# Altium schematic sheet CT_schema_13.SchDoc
size 629 x 471 mm
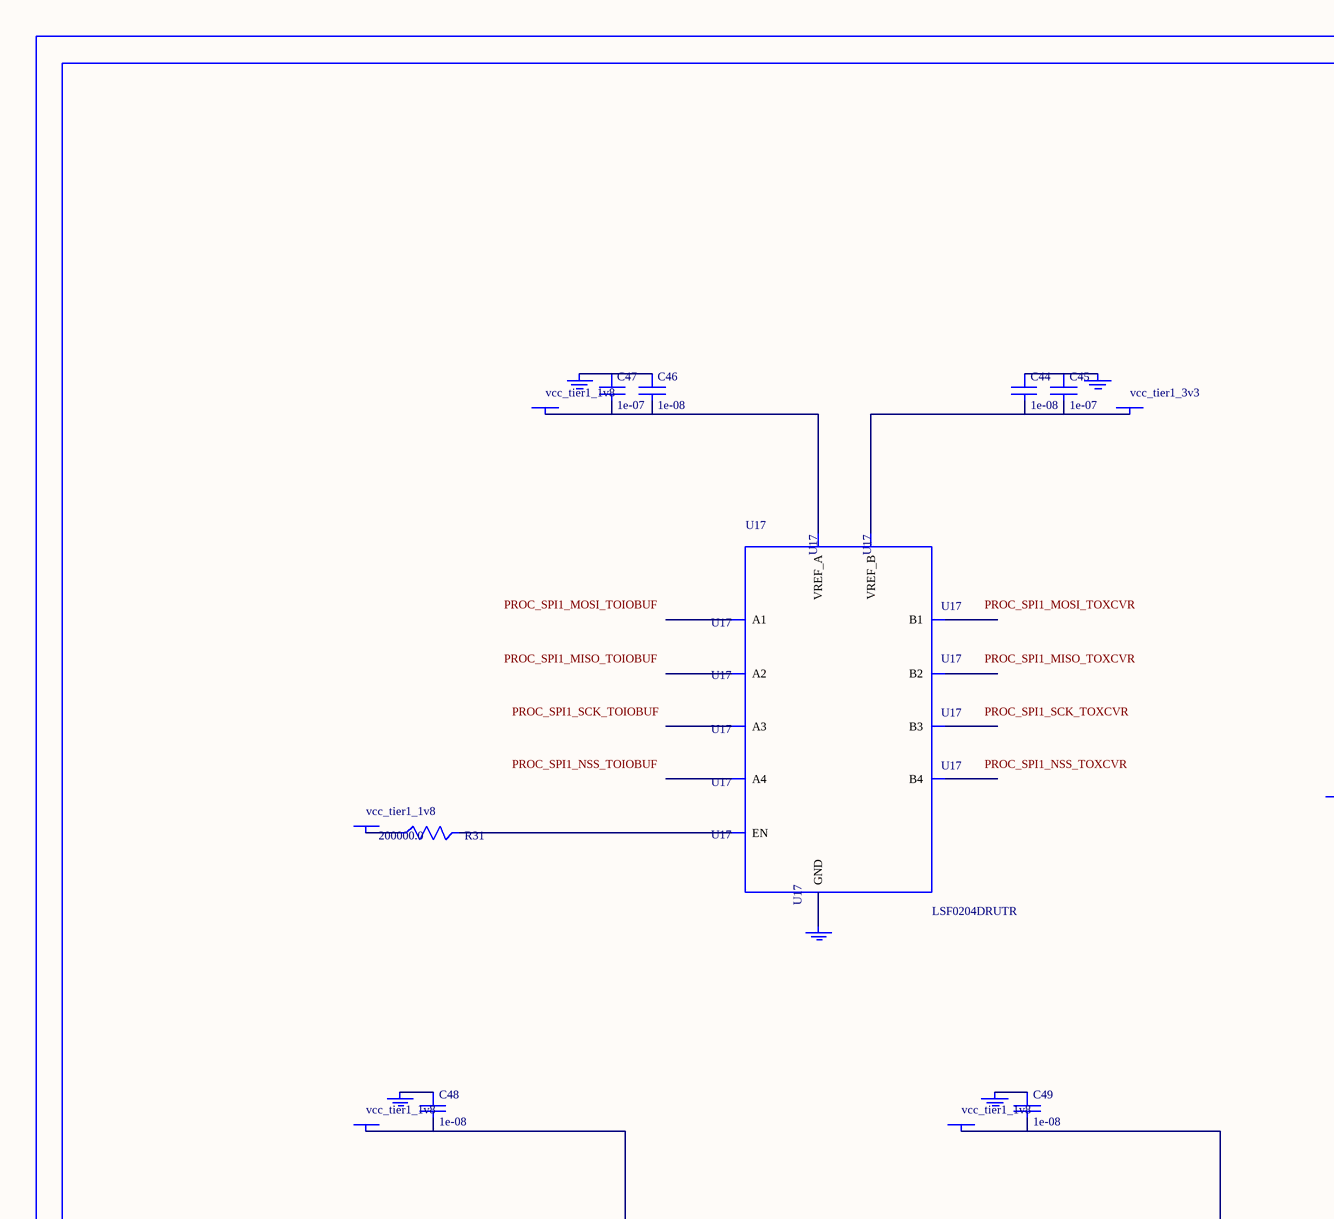
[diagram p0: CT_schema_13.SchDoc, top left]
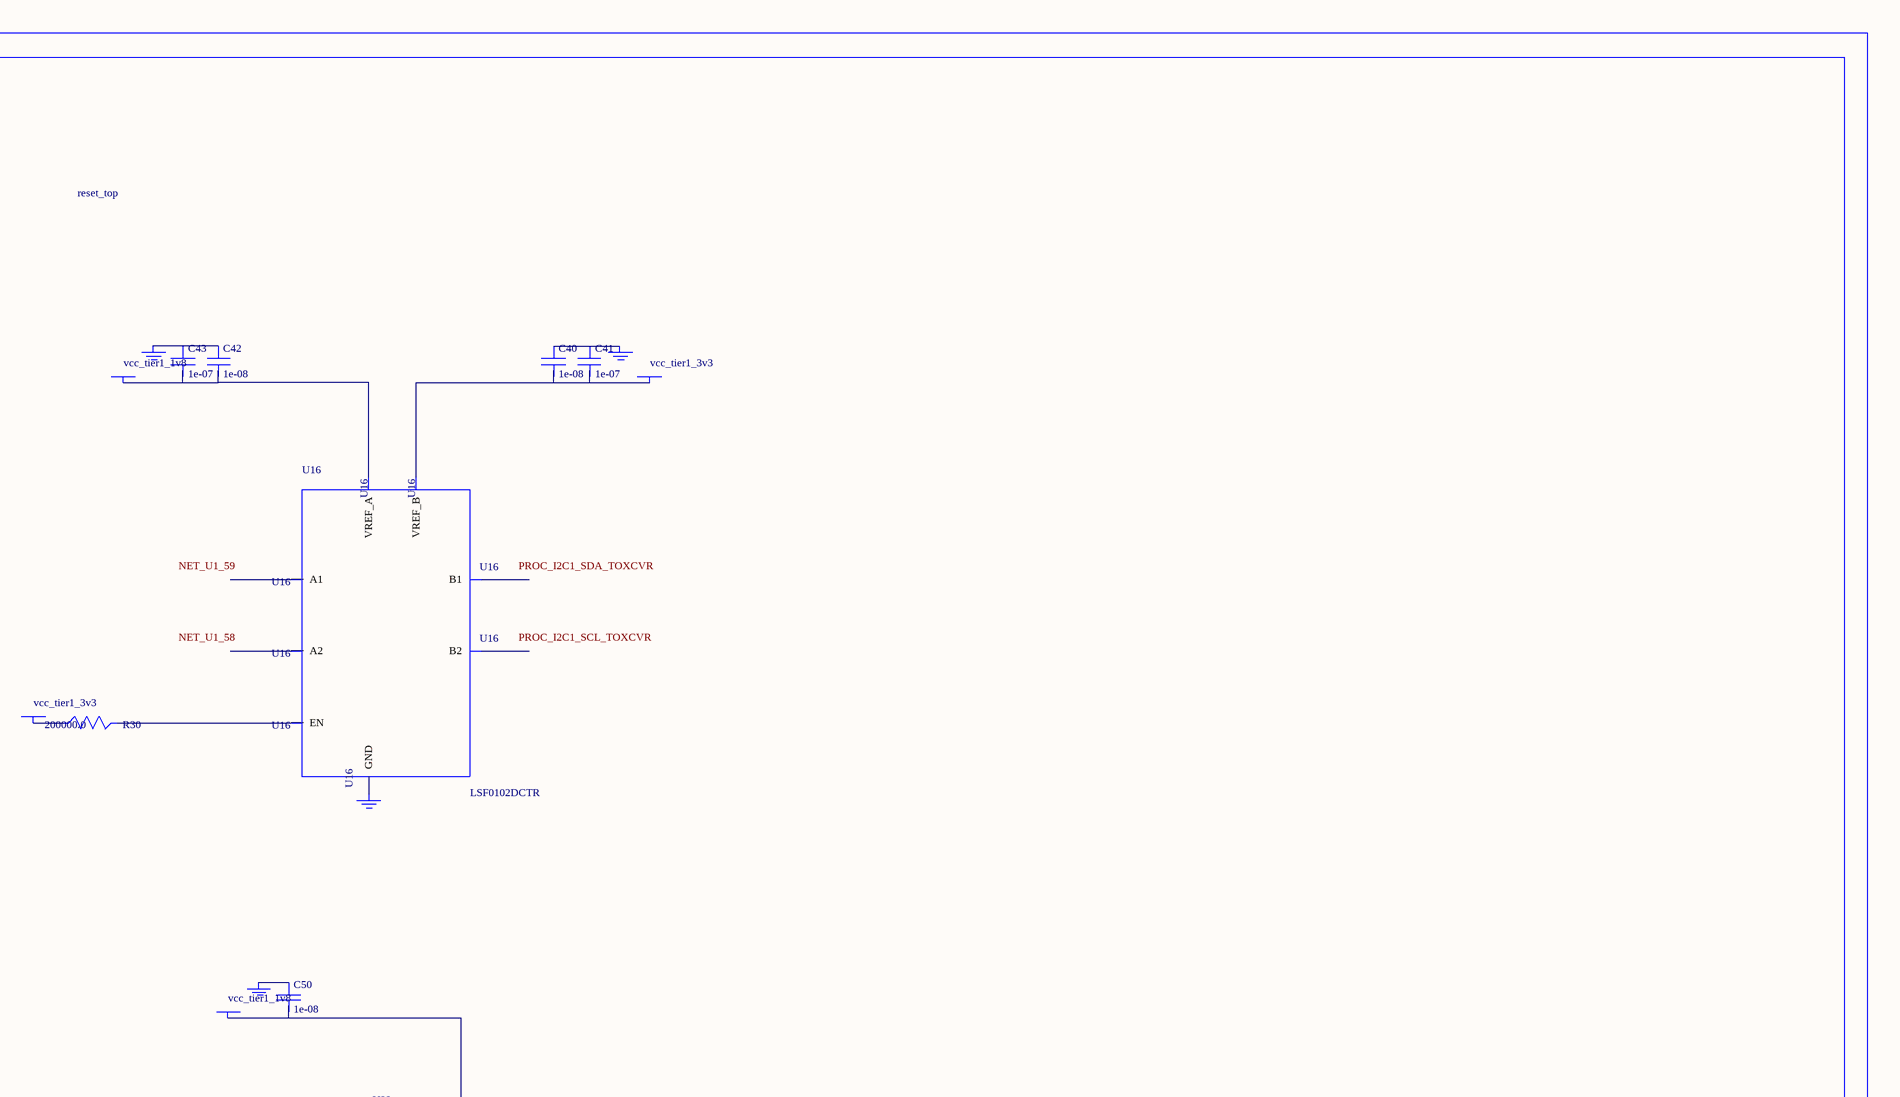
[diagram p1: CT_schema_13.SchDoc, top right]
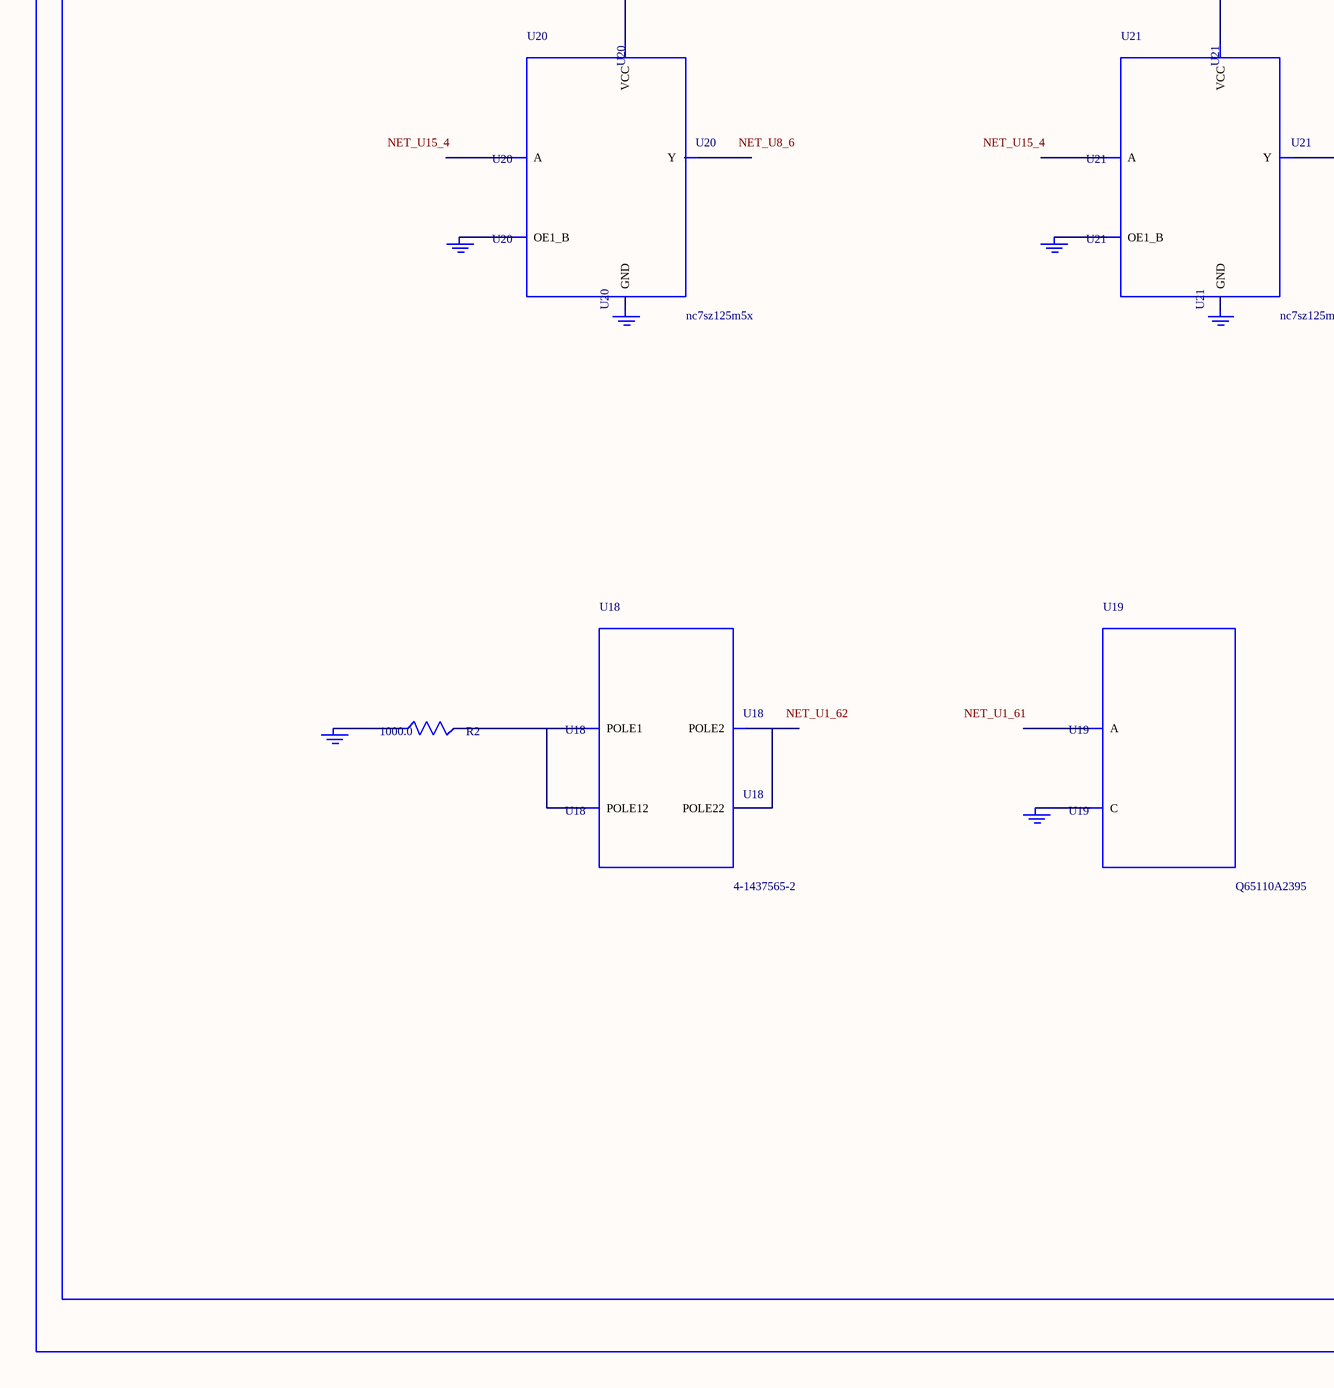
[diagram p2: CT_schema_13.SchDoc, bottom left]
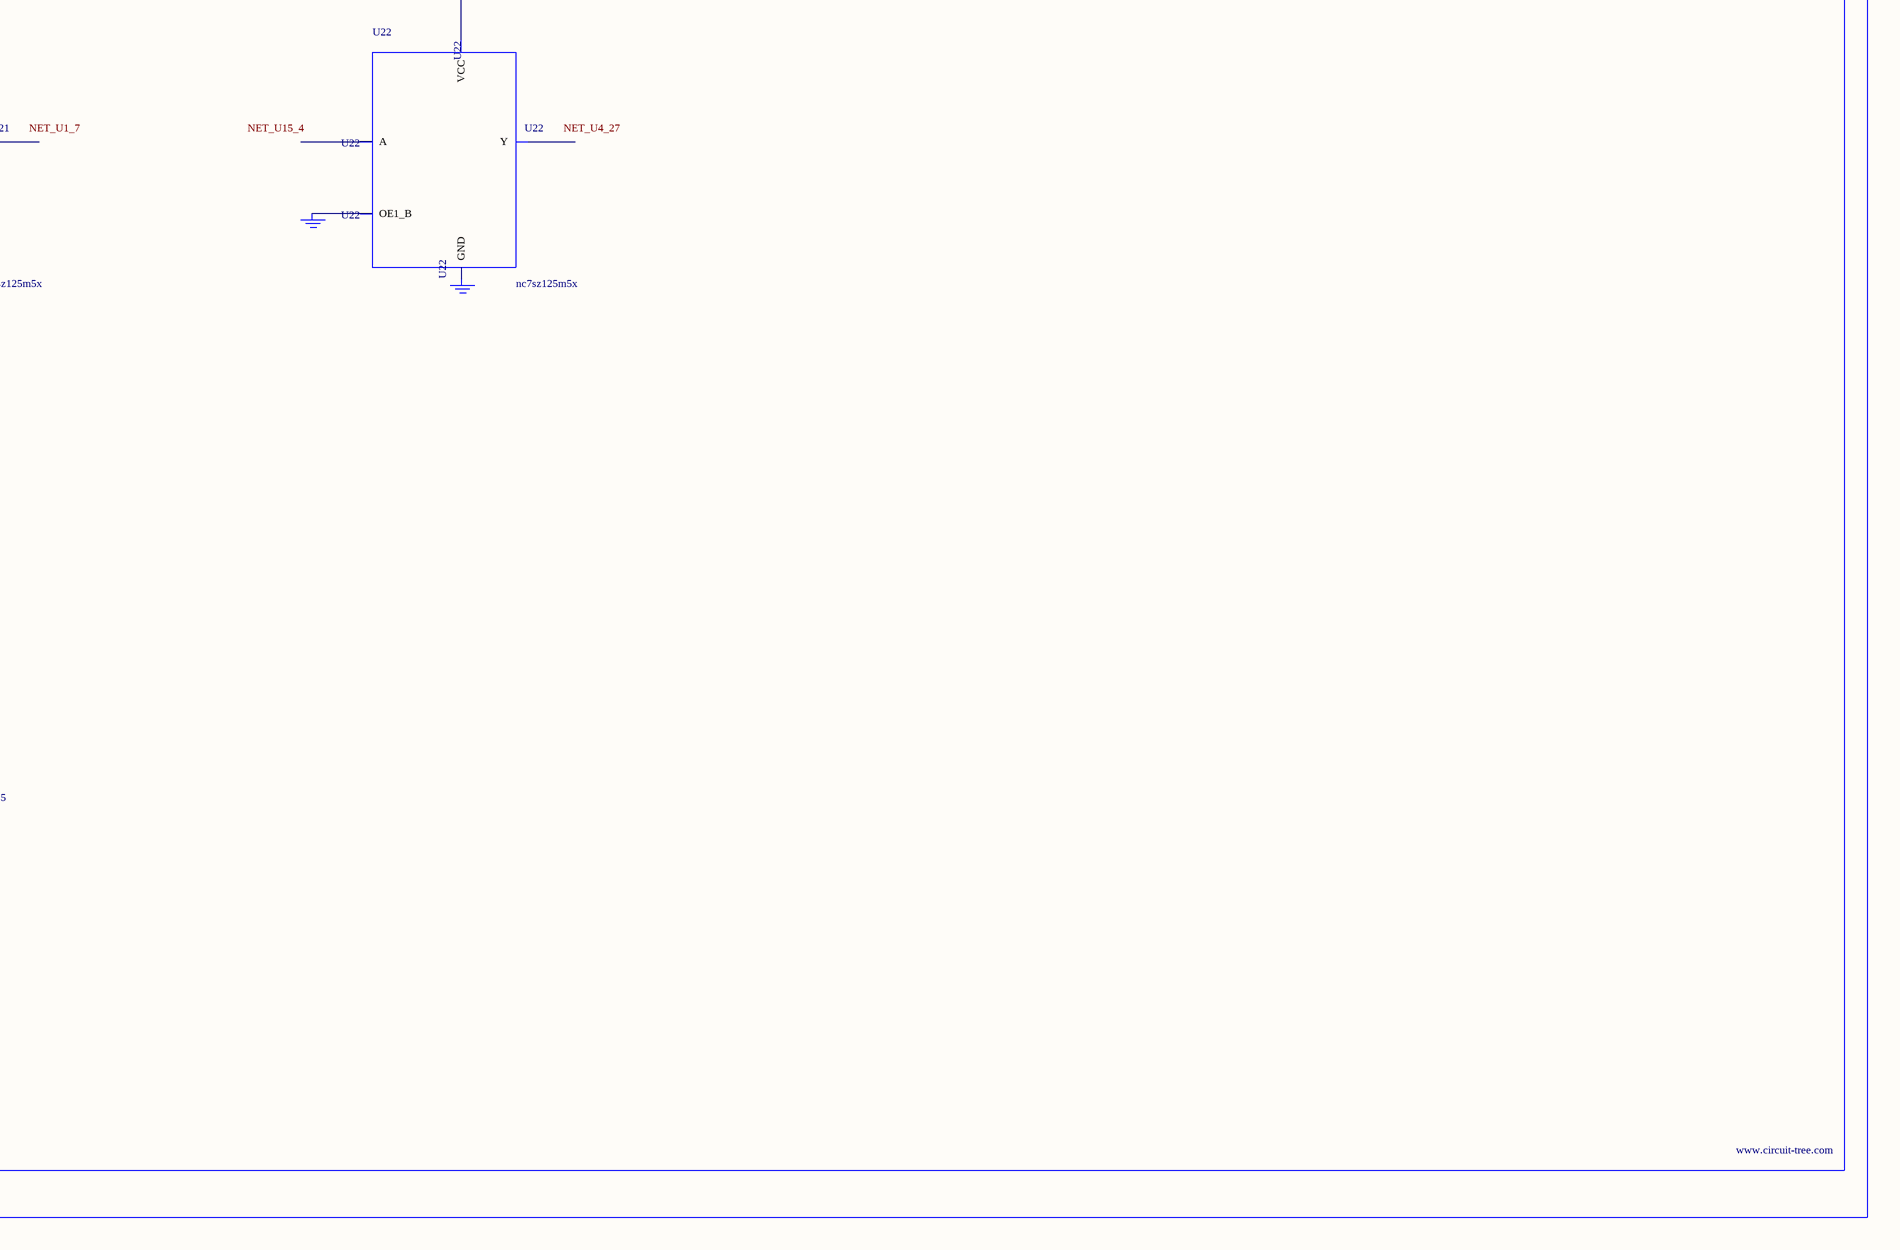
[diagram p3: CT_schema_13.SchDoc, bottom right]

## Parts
BORDER12  (no value)
C40  1e-08  [C0402]
C41  1e-07  [C0402]
C42  1e-08  [C0402]
C43  1e-07  [C0402]
C44  1e-08  [C0402]
C45  1e-07  [C0402]
C46  1e-08  [C0402]
C47  1e-07  [C0402]
C48  1e-08  [C0402]
C49  1e-08  [C0402]
C50  1e-08  [C0402]
GND_INSTANCE_12_0  (no value)
GND_INSTANCE_12_1  (no value)
GND_INSTANCE_12_2  (no value)
GND_INSTANCE_12_3  (no value)
GND_INSTANCE_12_4  (no value)
GND_INSTANCE_12_5  (no value)
GND_INSTANCE_12_6  (no value)
GND_INSTANCE_12_7  (no value)
GND_INSTANCE_12_8  (no value)
GND_INSTANCE_12_9  (no value)
GND_INSTANCE_12_10  (no value)
GND_INSTANCE_12_11  (no value)
GND_INSTANCE_12_12  (no value)
GND_INSTANCE_12_13  (no value)
GND_INSTANCE_12_14  (no value)
GND_INSTANCE_12_15  (no value)
GND_INSTANCE_12_16  (no value)
POWER_INSTANCE_12_0  vcc_tier1_1v8
POWER_INSTANCE_12_1  vcc_tier1_3v3
POWER_INSTANCE_12_2  vcc_tier1_3v3
POWER_INSTANCE_12_3  vcc_tier1_1v8
POWER_INSTANCE_12_4  vcc_tier1_3v3
POWER_INSTANCE_12_5  vcc_tier1_1v8
POWER_INSTANCE_12_6  vcc_tier1_1v8
POWER_INSTANCE_12_7  vcc_tier1_1v8
POWER_INSTANCE_12_8  vcc_tier1_1v8
R2  1000.0  [R0603]
R30  200000.0  [R0603]
R31  200000.0  [R0603]
U16  LSF0102DCTR  [DCU0008A_N]
U17  LSF0204DRUTR  [RUT0012A]
U18  4-1437565-2  [SW_4-1437565-2]
U19  Q65110A2395  [LGM67K-G1J2-24-Z]
U20  nc7sz125m5x  [NC7SZ125M5X]
U21  nc7sz125m5x  [NC7SZ125M5X]
U22  nc7sz125m5x  [NC7SZ125M5X]

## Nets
NetC40_1: C40.1 C41.1 GND_INSTANCE_12_1.0(GND)
NetC40_2: C40.2 C41.2 POWER_INSTANCE_12_1.0(PWR) U16.7(VREF_B)
NetC42_1: C42.1 C43.1 GND_INSTANCE_12_0.0(GND)
NetC42_2: C42.2 C43.2 POWER_INSTANCE_12_0.0(PWR) U16.2(VREF_A)
NetC44_1: C44.1 C45.1 GND_INSTANCE_12_4.0(GND)
NetC44_2: C44.2 C45.2 POWER_INSTANCE_12_4.0(PWR) U17.11(VREF_B)
NetC46_1: C46.1 C47.1 GND_INSTANCE_12_3.0(GND)
NetC46_2: C46.2 C47.2 POWER_INSTANCE_12_3.0(PWR) U17.1(VREF_A)
NetC48_1: C48.1 GND_INSTANCE_12_8.0(GND)
NetC48_2: C48.2 POWER_INSTANCE_12_6.0(PWR) U20.5(VCC)
NetC49_1: C49.1 GND_INSTANCE_12_11.0(GND)
NetC49_2: C49.2 POWER_INSTANCE_12_7.0(PWR) U21.5(VCC)
NetC50_1: C50.1 GND_INSTANCE_12_14.0(GND)
NetC50_2: C50.2 POWER_INSTANCE_12_8.0(PWR) U22.5(VCC)
NetGND_INSTANCE_12_2_0: GND_INSTANCE_12_2.0(GND) U16.1(GND)
NetGND_INSTANCE_12_5_0: GND_INSTANCE_12_5.0(GND) U17.6(GND)
NetGND_INSTANCE_12_6_0: GND_INSTANCE_12_6.0(GND) R2.1
NetGND_INSTANCE_12_7_0: GND_INSTANCE_12_7.0(GND) U19.C
NetGND_INSTANCE_12_9_0: GND_INSTANCE_12_9.0(GND) U20.1(OE1_B)
NetGND_INSTANCE_12_10_0: GND_INSTANCE_12_10.0(GND) U20.3(GND)
NetGND_INSTANCE_12_12_0: GND_INSTANCE_12_12.0(GND) U21.1(OE1_B)
NetGND_INSTANCE_12_13_0: GND_INSTANCE_12_13.0(GND) U21.3(GND)
NetGND_INSTANCE_12_15_0: GND_INSTANCE_12_15.0(GND) U22.1(OE1_B)
NetGND_INSTANCE_12_16_0: GND_INSTANCE_12_16.0(GND) U22.3(GND)
NetPOWER_INSTANCE_12_2_0: POWER_INSTANCE_12_2.0(PWR) R30.1
NetPOWER_INSTANCE_12_5_0: POWER_INSTANCE_12_5.0(PWR) R31.1
NetR2_2: R2.2 U18.1(POLE1) U18.2(POLE12)
NetR30_2: R30.2 U16.8(EN)
NetR31_2: R31.2 U17.12(EN)
NetU18_3: U18.3(POLE2) U18.4(POLE22)

Not connected (* = marked no-connect by the designer): U16 3(A1) 4(A2) 5(B2) 6(B1); U17 2(A1) 3(A2) 4(A3) 5(A4) 7(B4) 8(B3) 9(B2) 10(B1); U19 A; U20 2(A) 4(Y); U21 2(A) 4(Y); U22 2(A) 4(Y)

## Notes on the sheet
- Labels drawn without touching a wire or pin: NET_U1_7, NET_U1_58, NET_U1_59, NET_U1_61, NET_U1_62, NET_U4_27, NET_U8_6, NET_U15_4, PROC_I2C1_SCL_TOXCVR, PROC_I2C1_SDA_TOXCVR, PROC_SPI1_MISO_TOIOBUF, PROC_SPI1_MISO_TOXCVR, PROC_SPI1_MOSI_TOIOBUF, PROC_SPI1_MOSI_TOXCVR, PROC_SPI1_NSS_TOIOBUF, PROC_SPI1_NSS_TOXCVR, PROC_SPI1_SCK_TOIOBUF, PROC_SPI1_SCK_TOXCVR

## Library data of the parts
BORDER12 = BORDER_PAGE12
C40 C42 C44 C46 C48-C50 = C0402C103K3RAC
C41 C43 C45 C47 = C0402C104K3RACTU
GND_INSTANCE_12_0-GND_INSTANCE_12_16 = GND
POWER_INSTANCE_12_0-POWER_INSTANCE_12_8 = PWR
R2 = RC0603JR-071KL
R30 R31 = RC0603JR-07200KL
